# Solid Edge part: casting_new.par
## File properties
Author: CADSoft
Template: Sync Iso Part.par
Last saved by: CADSoft
Revision: 13
Application: Solid Edge
Accuracy: 0.990
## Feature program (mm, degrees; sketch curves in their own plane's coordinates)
sketch for "unnamed Hole 1" plane through (40.5572, 0.1779, 68) normal (0, 0, 1) x-axis (1, 0, 0)
  hole centre (-1.5572, -0.1779) bore radius 6
hole "unnamed Hole 1" through
sketch for "unnamed Hole 2" plane through (-40.5572, 0.1779, 68) normal (0, 0, 1) x-axis (-1, 0, 0)
  hole centre (-1.5572, -0.1779) bore radius 6
hole "unnamed Hole 2" through
pattern "unnamed Pattern 1" of "unnamed Hole 1", "unnamed Hole 2"
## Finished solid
Body 1: solid body, 47 faces, 120 edges, 76 vertices.
  Faces by surface: plane 35, cylinder 10, torus 2
  Edges by curve: line 94, circle 21, intersection 5
Bounding box of the edges (mm; curved faces can reach further): 200.000 x 56.000 x 68.000, from (-100, -28, 0) to (100, 28, 68).
Cylindrical faces by radius (mm): R3 x1, R5 x4, R6 x2, R24 x1, R54 x2
Toroidal faces (ring radius, tube radius in mm): R62 r8 x2
Planar faces by outward normal: +x 6, +y 6, +z 7, -x 6, -y 6, -z 4
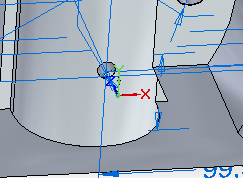
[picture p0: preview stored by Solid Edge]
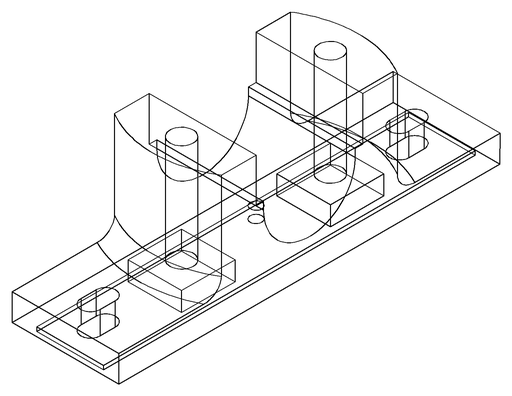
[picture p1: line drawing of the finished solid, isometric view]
